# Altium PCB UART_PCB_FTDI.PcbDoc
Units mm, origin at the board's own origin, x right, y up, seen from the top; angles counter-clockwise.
Board outline 25.4 x 30.58 mm, 2 copper layers (Top Layer, Bottom Layer), stack 1.6 mm thick; 18 components, 18 nets, 73 pads, 32 vias.
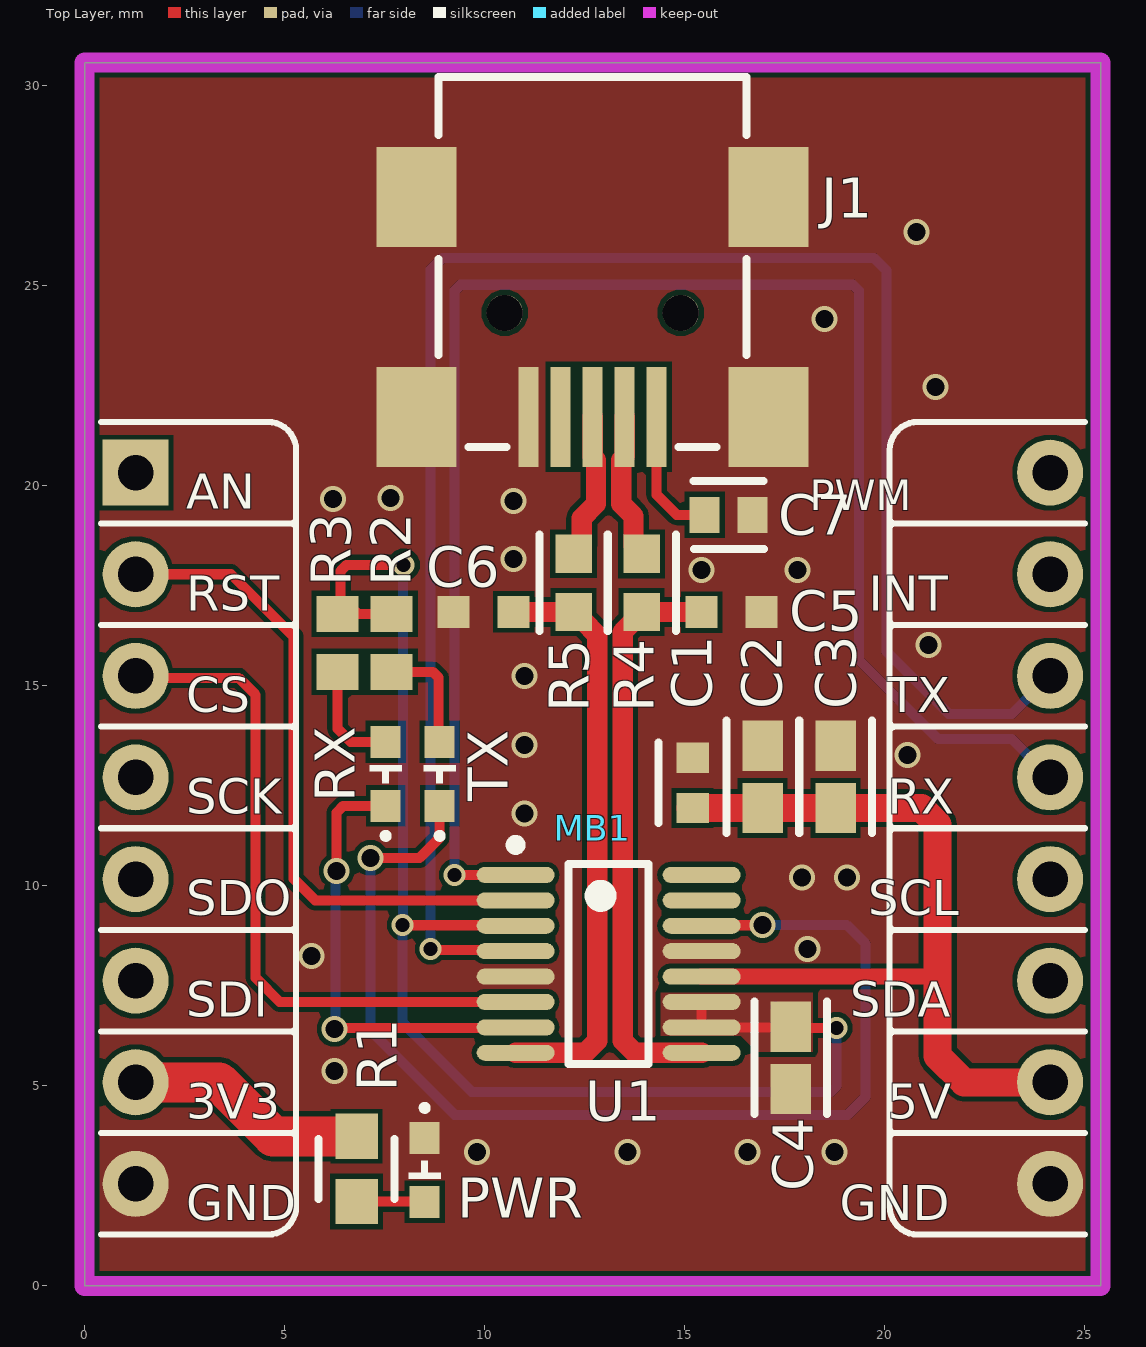
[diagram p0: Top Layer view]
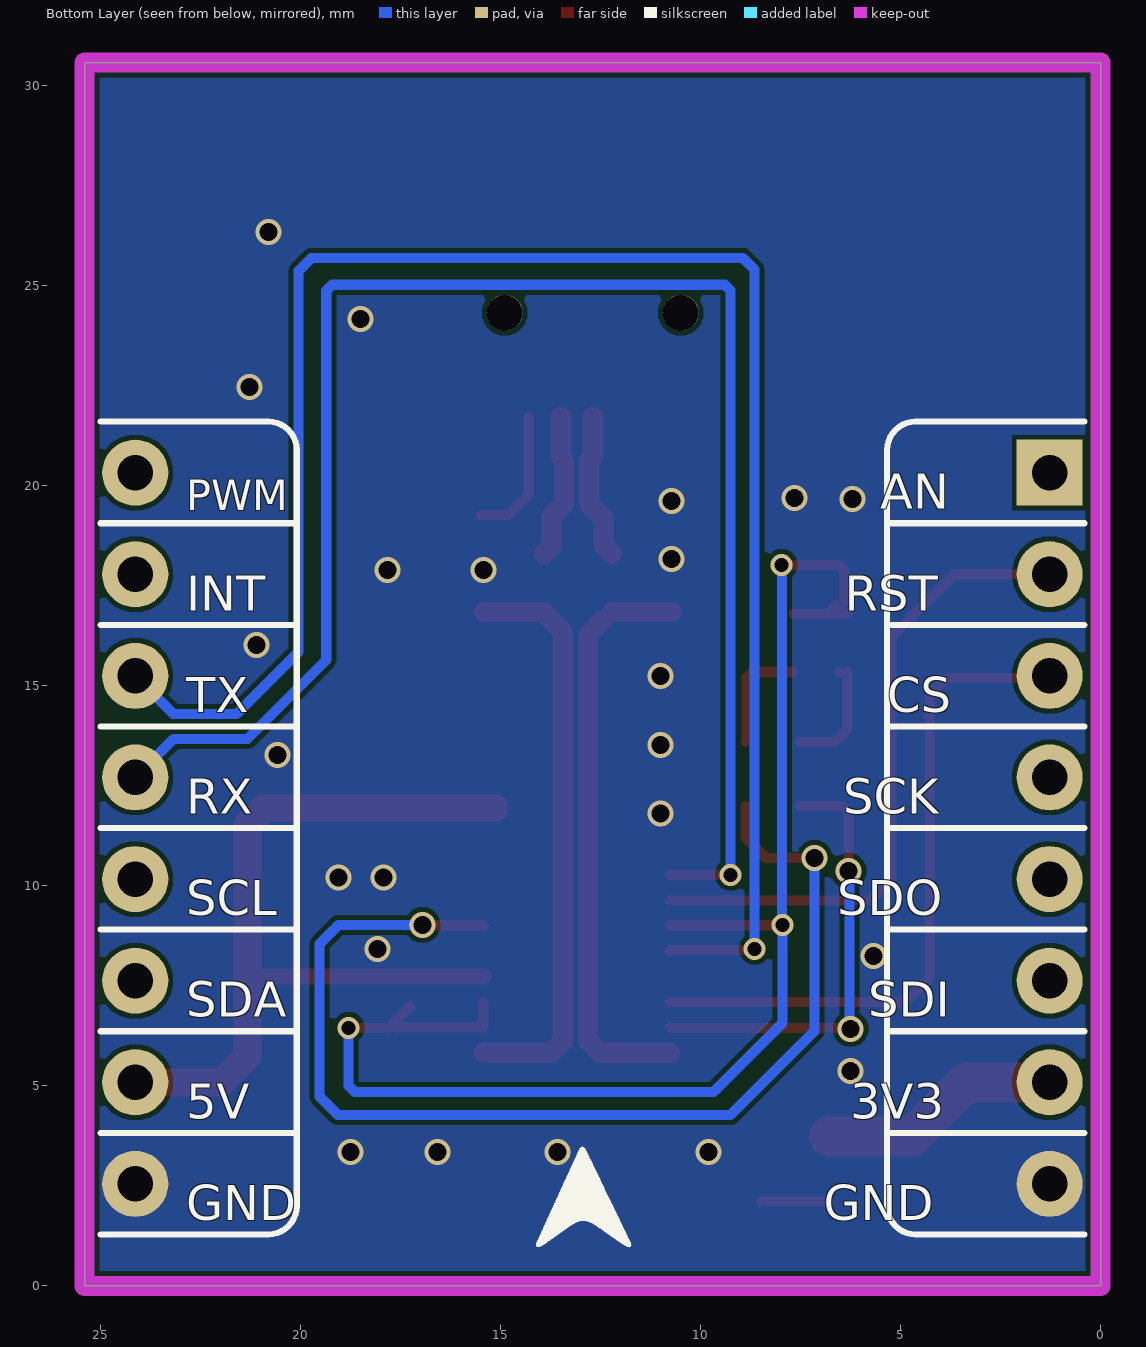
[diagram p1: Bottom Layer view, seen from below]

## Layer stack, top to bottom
Top Solder: solder mask 0.0102, Solder Resist, Dk 3.7
Top Layer: signal copper 0.035
Dielectric 1: dielectric 1.53, FR-4, Dk 4.1
Bottom Layer: signal copper 0.035
Bottom Solder: solder mask 0.0102, Solder Resist, Dk 3.7

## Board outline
0,0 0,30.58 25.4,30.58 25.4,0

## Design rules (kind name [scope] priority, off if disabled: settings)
Clearance [All] p1: gap=0.125 ignorepadtopadclearanceinfootprint=FALSE
DiffPairsRouting [All] p1: maxlimit=0.127 minlimit=0.127 mostfreqgap=0.127 toplayer_minwidth=0.506 toplayer_maxwidth=0.506 toplayer_prefwidth=0.506 bottomlayer_minwidth=0.506 bottomlayer_maxwidth=0.506 bottomlayer_prefwidth=0.506 impedanceprofiledriven=TRUE impedanceprofileid={C377098E-A32B-491C-BED3-60C399BF9EBD} impedanceprofilevalue=90.000000 maxuncoupledlength=12.7
HoleSize HoleSizeVia [IsVia] p1: absolutevalues=TRUE maxlimit=0.45 minlimit=0.25 maxpercent=80.000 minpercent=20.000
HoleSize HoleSizePTH [IsPad] p2: absolutevalues=TRUE maxlimit=5.6 minlimit=0.5 maxpercent=80.000 minpercent=20.000
HoleToHoleClearance [All] p1: gap=0.3 allowstackedmicrovias=TRUE
MinimumAnnularRing MinimumAnnularRingVias [All] p1: minimumring=0.1
MinimumAnnularRing MinimumAnnularRingGeneral [All] p2: minimumring=0.3
MinimumSolderMaskSliver [All] p1: minsoldermaskwidth=0.08
PasteMaskExpansion [All] p1: expansion=0.085
PolygonConnect [All] p1: connectstyle=Direct reliefconductorwidth=0.254 reliefentries=4 polygonreliefangle="90 Angle" airgapwidth=0.254
RoutingVias [All] p1: holewidth=0.35 width=0.55 viastyle="Through Hole" minholewidth=0.3 minwidth=0.5 maxholewidth=0.45 maxwidth=0.65
SilkToSilkClearance SilkToSilkClerance [All] p1: silktosilkclearance=0.125
SilkToSolderMaskClearance [IsPad] p1: minsilkscreentomaskgap=0.125 clearancetoexposedcopper=TRUE
SolderMaskExpansion SolderMaskExpansionVia [IsVia] p1: expansion=0.1 istentingtop=TRUE useseparateexpansions=TRUE expansionbottom=0.1 istentingbottom=TRUE
SolderMaskExpansion [All] p2: expansion=0.075 istentingtop=FALSE
SupplyNets "Schematic Supply Nets_2" [InNet('+3V3')] p1: voltage=0.000
SupplyNets "Schematic Supply Nets_1" [InNet('GND')] p2: voltage=0.000
SupplyNets "Schematic Supply Nets" [InNet('+5')] p3: voltage=0.000
UnRoutedNet [All] p1: checkbadconnections=TRUE
Width [All] p1: maxlimit=2.54 minlimit=0.125 preferedwidth=0.254
22 further rules are at their usual default settings.

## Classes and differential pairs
differential pair USB_F: +USB_F_P -USB_F_N
differential pair USB: +USB_P -USB_N

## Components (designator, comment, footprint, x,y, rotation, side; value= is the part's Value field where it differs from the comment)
C1 "4.7uF" FP-CL10-IPC_C 15.2,12.575 r90 top
C2 "0.1uF" FP-CC0603-DA-IPC_A 16.95,12.725 r90 top
C3 "0.1uF" FP-CC0603-DA-IPC_A 18.775,12.725 r90 top
C4 "0.1uF" FP-CC0603-DA-IPC_A 17.65,5.698 r90 top
C5 "47pF" WCAP-CSGP_0603_L1.6W0.8H0.8_Reflow 16.175,16.846 r0 top
C6 "47pF" WCAP-CSGP_0603_L1.6W0.8H0.8_Reflow 9.975,16.848 r180 top
C7 "10nF" FP-C0603C-CF-MFG 16.1,19.275 r0 top value="10,000 pF"
J1 "65100516121" 65100516121 12.7,25.6 r180 top
MB1 "Embedd_Sensor_Schields" "Embedd_add_on_board_25,4 x 30,58" 0.005,0.01 r0 top locked
PWR "150060GS55040" WL-SMCD_0603 1278.5,-1267.1 r270 top
R1 "33" FP-CRCW0603-e3-IPC_A 6.8,2.925 r90 top
R2 "270" RESC1608X55X30ML15T15 7.675,16.075 r90 top
R3 "270" RESC1608X55X30ML15T15 6.325,16.075 r90 top
R4 "27" FP-ESR03-IPC_B 13.925,17.573 r270 top
R5 "27" FP-ESR03-IPC_B 12.225,17.575 r270 top
RX "150060GS55040" WL-SMCD_0603 -1262.475,1282.8 r90 top
TX "150060GS55040" WL-SMCD_0603 -1261.125,1282.8 r90 top
U1 "FT230XS-U" SSOP-16_L 13.1,8.05 r0 top

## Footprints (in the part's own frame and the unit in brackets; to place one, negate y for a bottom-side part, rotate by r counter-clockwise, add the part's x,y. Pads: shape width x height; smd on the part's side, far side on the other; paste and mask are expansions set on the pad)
65100516121 [mm] "Mini USB 2.0 Type B SMT Horizontal 5 Contacts"
  rect 0.5x2.5 smd: 1(-1.6,3.875) 2(-0.8,3.875) 3(0,3.875) 4(0.8,3.875) 5(1.6,3.875)
  round 0.9 hole 0.9 unplated: MH1(-2.2,1.275) MH2(2.2,1.275)
  rect 2x2.5 smd: Shell(-4.4,3.875) Shell(-4.4,-1.625) Shell(4.4,3.875) Shell(4.4,-1.625)
  silkscreen extent -3.85,-4.62 3.85,4.62, body extent -4.8,-4.62 4.8,4.63, height 3.92
"Embedd_add_on_board_25,4 x 30,58" [mil] "Medium footprint"
  rect 65x65 hole 35: 1(50,800)
  round 65 hole 35: 2(50,700) 3(50,600) 4(50,500) 5(50,400) 6(50,300) 7(50,200) 8(50,100) 9(950,100) 10(950,200) 11(950,300) 12(950,400) 13(950,500) 14(950,600) 15(950,700) 16(950,800)
  silkscreen extent 16,50 984,850, body extent 0,51 1000,851, height 103
FP-C0603C-CF-MFG [mm]
  rect 0.75x0.9 smd paste+0 mask+0: 1(-0.6,0) 2(0.6,0)
  silkscreen extent -0.87,-0.85 0.88,0.85, body extent -1.2,-0.6 1.2,0.6, height 0.25
FP-CC0603-DA-IPC_A [mm]
  rect 1.258x1.012 smd paste+0 mask+0: 1(-0.777,0) 2(0.777,0)
  silkscreen extent -1.41,-0.91 1.41,0.91, body extent -1.91,-1.01 1.91,1.01, height 0.25
FP-CL10-IPC_C [mm]
  rect 0.758x0.812 smd paste+0 mask+0: 1(-0.627,0) 2(0.627,0)
  silkscreen extent -1.01,-0.85 1.01,0.85, body extent -1.11,-0.55 1.11,0.55, height 0.25
FP-CRCW0603-e3-IPC_A [mm]
  rect 1.135x1.062 smd paste+0 mask+0: 1(-0.815,0) 2(0.815,0)
  silkscreen extent -0.75,-0.95 0.75,0.95, body extent -1.88,-1.03 1.88,1.03, height 0.25
FP-ESR03-IPC_B [mm]
  rect 0.958x0.912 smd paste+0 mask+0: 1(-0.727,0) 2(0.727,0)
  silkscreen extent -1.21,-0.86 1.21,0.86, body extent -1.46,-0.71 1.46,0.71, height 0.25
RESC1608X55X30ML15T15 [mm] "Chip Resistor, 2-Leads, Body 1.60x0.80mm, IPC Low Density"
  rect 0.9x1.05 smd: 1(-0.725,0) 2(0.725,0)
  body extent -0.87,-0.48 0.87,0.48, height 0.55
SSOP-16_L [mm] "SOP, 16-Leads, Body 4.9x3.9mm, Pitch 0.635mm, IPC High Density"
  oval 1.95x0.4 smd: 1(-2.325,2.222) 2(-2.325,1.587) 3(-2.325,0.953) 4(-2.325,0.318) 5(-2.325,-0.318) 6(-2.325,-0.953) 7(-2.325,-1.587) 8(-2.325,-2.222) 9(2.325,-2.222) 10(2.325,-1.587) 11(2.325,-0.953) 12(2.325,-0.318) 13(2.325,0.318) 14(2.325,0.953) 15(2.325,1.587) 16(2.325,2.222)
  silkscreen extent -2.45,-2.5 1,3.1, body extent -1.99,-2.5 1.99,2.5, height 1.76
WCAP-CSGP_0603_L1.6W0.8H0.8_Reflow [mm] "Ceramic Capacitors, body 1.6x0.8mm"
  rect 0.8x0.8 smd: 1(-0.75,0) 2(0.75,0)
  body extent -0.8,-0.4 0.8,0.4, height 0.8
WL-SMCD_0603 [mm] "SMD Mono-color Chip LED, body 1.6x0.8mm"
  rect 0.8x0.75 smd: 1(-1270.8,-1270) 2(-1269.2,-1270)
  silkscreen extent -1271.62,-1270.4 -1269.78,-1269.6, body extent -1270.8,-1270.4 -1269.2,-1269.6, height 0.42

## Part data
C1: library part CMP-13271-003017-1, "Cap Ceramic 4.7uF 10V X5R ±10% Pad SMD 0603 +85°C T/R", Case Code (Imperial)=0603, Case Code (Metric)=1608, Dielectric=X5R, Max Operating Temperature=85°C, Min Operating Temperature=-55°C, Package Quantity=1, Tolerance=10%, Voltage Rating=10V
C2 C3 C4: library part CMP-03422-001490-1, "CAP CER 0.1UF 50V X7R 0603", Capacitance=100nF, Case Code (Imperial)=0603, Case Code (Metric)=1608, Dielectric=X7R, Max Operating Temperature=125°C, Min Operating Temperature=-55°C, Resistor Type=Ceramic, Tolerance=5%, Voltage Rating=50V
C5 C6: library part CMP-03913-65419532-1, "885012006006 Ceramic Capacitor 47pF, 10VDC, 0603, ±5 %", Case Code (Imperial)=0603, Case Code (Metric)=1608, Insulation Resistance=10GΩ, Max Operating Temperature=125°C, Min Operating Temperature=-55°C, Tolerance=5%, Voltage Rating=10V
C7: library part CMP-2006-03036-2, "CAP CER 10000PF 100V X7R 0603", Capacitance="10,000 pF", Manufacturer=KEMET, Manufacturer Part Number=C0603C103K1RACTU, Package=C0603C-CF, Temperature="-55°C to +125°C", Temperature Characteristic=X7R, Temperature Coefficient=30ppm/°C, Temperature Range High=+125°C, Temperature Range Low=-55°C, Tolerance=0.1, Voltage Rating="100 V"
J1: library part CMP-2000-05576-3, Color=Black, Contact Resistance=20mΩ, Current Rating=1A, Flammability Rating="UL94 V-0", Insulation Resistance=1GΩ, Max Operating Temperature=105°C, Min Operating Temperature=-40°C, Operating Supply Voltage=30V
MB1: library part CMP-00030-00005-3, "Footprint for sensor shields", Max Operating Temperature=85°C, Min Operating Temperature=-40°C
PWR RX TX: library part CMP-03913-90235563-2, "150060GS55040 WL-SMCD SMT Mono-color Chip LED Diffused", Forward Current=60mA, Forward Voltage=3.2V, Max Operating Temperature=85°C, Max Reverse Voltage (DC)=5V, Min Operating Temperature=-40°C
R1: library part CMP-2000-03250-2, "RES Thick Film, 33Ω, 1%, 0.1W, 100ppm/°C, 0603", Case Code (Imperial)=0603, Case Code (Metric)=1608, Max Operating Temperature=155°C, Max Power Dissipation=100mW, Min Operating Temperature=-55°C, Package Quantity=10, Resistance=33R, Temperature Coefficient=100ppm/°C, Tolerance=1%, Voltage Rating=75V
R2 R3: library part CMP-2000-00758-1, Manufacturer=Panasonic, Part Number=ERJ-3GEYJ271V
R4 R5: library part CMP-08839-028859-1, "27Ω ±0.5% 0.25W 0603 Anti-Surge Chip Resistor AEC-Q200"
U1: library part CMP-0248-00025-2, "USB to Basic UART Interface Chip, UHCI/OHCI/EHCI Compatible, USB 2.0 Compatible, -40 to +85 degC, 16-Pin SSOP, Pb-Free, Tube", Manufacturer=FTDI

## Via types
v1: diameter 0.65, hole 0.45, Top Layer to Bottom Layer, tented both sides, 27 vias
v2: diameter 0.55, hole 0.35, Top Layer to Bottom Layer, tented both sides, 5 vias

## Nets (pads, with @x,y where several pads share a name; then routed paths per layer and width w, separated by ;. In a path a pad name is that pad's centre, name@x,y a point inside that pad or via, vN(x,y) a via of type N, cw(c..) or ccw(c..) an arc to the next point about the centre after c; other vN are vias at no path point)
3V3OUT: C4.2 R2.2 R3.2 U1.3 U1.10 U1.11 | length 36.3
  Top Layer w0.254: R3.2 R3.2@6.825,16.8 ; R2.2 R3.2@6.825,16.8 ; v2(7.95,9.025) 7.961,9.014 10.764,9.014 U1.3 ; v2(7.975,18.025) 6.55,18.025 6.4,17.875 6.4,17.123 6.511,17.013 6.612,17.013 R3.2@6.825,16.8 ; U1.11 U1.10 C4.2@17.637,6.462 ; C4.2@17.271,6.977 17.798,6.45 v2(18.8,6.45)
  Bottom Layer w0.254: v2(7.975,18.025) 7.963,18.013 7.963,9.118 7.95,9.105 7.95,6.575 9.675,4.85 18.651,4.85 18.8,4.999 v2(18.8,6.45)
+3V3: MB1.7 R1.2 | length 6.1
  Top Layer w1: MB1.7 3.36,5.09 4.71,3.74 R1.2
+5V: C1.1 C2.1 C3.1 MB1.10 U1.12 | length 21.1
  Top Layer w0.4: U1.12 21.268,7.732
  Top Layer w0.7: C1.1@15.15,11.948 C2.1 C3.1 20.915,11.948 21.325,11.538 21.325,7.675 ; 21.268,7.732 21.325,7.675 ; MB1.10 21.985,5.09 21.325,5.75 21.325,7.675
GND: C1.2 C2.2 C3.2 C4.1 C5.2 C6.2 C7.2 J1.5 J1.Shell MB1.8 MB1.9 PWR.1 U1.5 U1.13
  other v1: 9.806,3.35 13.575,3.35 16.575,3.35 18.75,3.35 6.25,5.375 5.675,8.25 18.075,8.425 17.931,10.206 19.056,10.206 11,11.806 20.575,13.275 11,13.525 11,15.245 21.1,16.025 15.425,17.9 17.825,17.9 10.725,18.175 10.725,19.625 6.206,19.67 7.65,19.7 21.275,22.475 18.5,24.175 20.8,26.35
NetMB1_2: MB1.2 U1.2 | length 16.4
  Top Layer w0.254: MB1.2 3.66,17.79 5.225,16.225 5.225,10.175 5.763,9.637 U1.2
NetMB1_3: MB1.3 U1.6 | length 17
  Top Layer w0.254: MB1.3 1.325,15.2 3.85,15.2 4.275,14.775 4.275,7.7 4.878,7.097 U1.6
NetMB1_13: MB1.13 U1.1 | length 41.6
  Top Layer w0.254: v2(9.25,10.275) v2(9.25,10.275) 10.774,10.274 U1.1
  Bottom Layer w0.254: v2@9.25,10.297 9.25,24.878 9.399,25.027 19.209,25.027 19.36,24.876 19.36,15.647 21.331,13.675 23.17,13.675 MB1.13
NetMB1_14: MB1.14 U1.4 | length 45.4
  Top Layer w0.254: v2(8.65,8.425) 8.68,8.395 10.747,8.395 U1.4
  Bottom Layer w0.254: v2(8.65,8.425) 8.65,25.401 8.949,25.7 19.726,25.7 20.05,25.376 20.05,15.85 21.6,14.3 23.185,14.3 MB1.14
NetPWR_2: PWR.2 R1.1 | length 1.7
  Top Layer w0.254: R1.1 8.49,2.11 PWR.2
NetR2_1: R2.1 TX.2 | length 2.8
  Top Layer w0.254: R2.1 8.701,15.35 8.85,15.201 8.85,13.625 TX.2
NetR3_1: R3.1 RX.2 | length 2.8
  Top Layer w0.254: R3.1 6.325,13.925 6.65,13.6 RX.2
NetRX_1: RX.1 U1.7 | length 11.3
  Top Layer w0.254: v1(6.25,6.425) 6.269,6.444 10.756,6.444 U1.7 ; v1(6.3,10.375) 6.3,11.836 6.464,12 RX.1
  Bottom Layer w0.254: v1(6.25,6.425) 6.275,6.45 6.275,10.35 v1(6.3,10.375)
NetTX_1: TX.1 U1.14 | length 28.6
  Top Layer w0.254: v1(7.15,10.7) 8.375,10.7 8.875,11.2 TX.1 ; U1.14 15.436,9.014 16.939,9.014 v1(16.95,9.025)
  Bottom Layer w0.254: v1(7.15,10.7) 7.15,6.375 9.25,4.275 19.075,4.275 19.525,4.725 19.525,8.55 19.05,9.025 v1(16.95,9.025)
USB_5V: C7.1 J1.1 | length 3.4
  Top Layer w0.254: J1.1 14.3,19.775 14.8,19.275 C7.1
USB_F_N: C5.1 R4.2 U1.9 | length 14.5
  Top Layer w0.506: U1.9 13.747,5.827 13.45,6.124 13.45,16.348 13.925,16.823 R4.2 C5.1
USB_F_P: C6.1 R5.2 U1.8 | length 14.3
  Top Layer w0.506: C6.1 R5.2 ; U1.8 12.52,5.827 12.817,6.124 12.817,16.267 R5.2@12.462,16.622
USB_N: J1.2 R4.1 | length 3.7
  Top Layer w0.506: J1.2 13.5,20.731 13.417,20.648 13.417,19.55 13.722,19.245 13.722,18.503 R4.1
USB_P: J1.3 R5.1 | length 3.7
  Top Layer w0.506: R5.1 12.428,18.505 12.428,19.195 12.783,19.55 12.783,20.648 12.7,20.731 J1.3
pads on no net: J1.4 J1.MH1 J1.MH2 MB1.1 MB1.4 MB1.5 MB1.6 MB1.11 MB1.12 MB1.15 MB1.16 U1.15 U1.16

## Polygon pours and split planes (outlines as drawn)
GND on Top Layer "GND_L01_P001" (solid, remove dead copper, pour order 1): 0,0 0,30.58 25.4,30.58 25.4,0
3V3OUT on Top Layer "NONET_L-01_P-001" (solid, remove dead copper, pour order 0): 14.4,7.325 18.2,7.325 18.2,5.85 16.8,5.85 16.4,6.25 14.4,6.25
GND on Bottom Layer "GND_L02_P002" (solid, remove dead copper, pour order 2): 0,0 0,30.58 25.4,30.58 25.4,0

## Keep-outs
Keep-Out Layer:
  the board outline again, w0.5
